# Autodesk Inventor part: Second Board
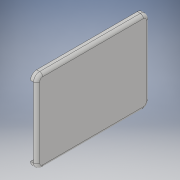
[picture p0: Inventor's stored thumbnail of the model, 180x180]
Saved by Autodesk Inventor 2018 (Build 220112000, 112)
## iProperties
Created: 2017-07
Part Number: Second Board
Material: Generic
Document SubType Name: Modeling
Designer: 17046589
Density: 1 g/cm^3
Appearance: Default
Mass: 1251.09 g
Surface Area: 2420.44 cm^2
Volume: 1251.09 cm^3
Author: 17046589
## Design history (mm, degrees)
sketch "Sketch1"
  geometry: L1 (0, 0)-(-270, 0); L2 (-270, 0)-(-270, 370); L3 (-270, 370)-(0, 370); L4 (0, 370)-(0, 0)
  constraints: 8 end point, 2 parallel, 1 horizontal, 1 perpendicular
  dimensions: "d0" = 270 distance of L2.end L3.end; "d1" = 370 distance of L1.end L2.end
extrude "Extrusion1" new body sketch "Sketch1" distance "d2" = 20; taper "d3" = 0 deg
fillet "Fillet1" dims "d4" = 20
fillet "Fillet2" dims "d5" = 20
fillet "Fillet3" dims "d6" = 20
fillet "Fillet4" dims "d7" = 20
fillet "Fillet5" dims "d8" = 10
sketch "Sketch2"
  geometry: L1 (0, -20)-(0, -250) reference; L2 (0, -20)-(0, -250.001); L3 (10, -20)-(10, -250) reference; L4 (370, -250)-(370, -20) reference; L5 (370, -250.001)-(370, -20); L6 (370, -20)-(0, -20); 1 further point; 1 other entity
  constraints: 6 end point, 1 collinear, 1 parallel, 1 perpendicular, 1 vertical, 3 other
extrude "Extrusion2" cut sketch "Sketch2" distance "d9" = 10; taper "d10" = 0 deg
sketch "Sketch3"
  geometry: L1 (0, 0)-(0, 370) reference; L2 (0, 19.618)-(10, 19.618); L3 (20, 350)-(10, 350) reference; L4 (10, 19.618)-(10, 350); L5 (10, 350)-(0, 350); L6 (0, 350)-(0, 19.618)
  constraints: 8 end point, 4 perpendicular, 1 point on line
extrude "Extrusion3" join sketch "Sketch3" distance "d11" = 40; taper "d12" = 0 deg
sketch "Sketch4"
  geometry: L1 (23.899, -219.544)-(23.899, -233.316); L2 (23.899, -233.316)-(348.759, -233.316); L3 (348.759, -233.316)-(348.759, -219.544); L4 (348.759, -219.544)-(23.899, -219.544); L5 (23.899, -183.898)-(23.899, -198.481); L6 (23.899, -198.481)-(348.759, -198.481); L7 (348.759, -198.481)-(348.759, -183.898); L8 (348.759, -183.898)-(23.899, -183.898); 1 further point
  constraints: 16 end point, 5 perpendicular, 4 point on line, 1 vertical
extrude "Extrusion4" join sketch "Sketch4" distance "d13" = 10; taper "d14" = 0 deg
sketch "Sketch5"
  geometry: L1 (26.607, -23.65)-(26.607, -35.475); L2 (26.607, -35.475)-(342.123, -35.475); L3 (342.123, -35.475)-(342.123, -23.65); L4 (342.123, -23.65)-(26.607, -23.65); 1 further point
  constraints: 8 end point, 3 perpendicular, 1 vertical
extrude "Extrusion5" cut sketch "Sketch5" distance "d15" = 10; taper "d16" = 0 deg
sketch "Sketch6"
  geometry: L1 (0, 19.618)-(10, 19.618) reference; L2 (0, 19.618)-(10, 19.618); L3 (10, 350)-(10, 19.618) reference; L4 (10, 19.618)-(10, 350); L5 (10, 350)-(0, 350); L6 (0, 350)-(0, 19.618); L7 (0, 342.123)-(0, 26.607) reference; 1 further point
  constraints: 8 end point, 2 collinear, 1 horizontal, 1 perpendicular
extrude "Extrusion6" cut sketch "Sketch6" distance "d17" = 15; taper "d18" = 0 deg
body "Solid1"
